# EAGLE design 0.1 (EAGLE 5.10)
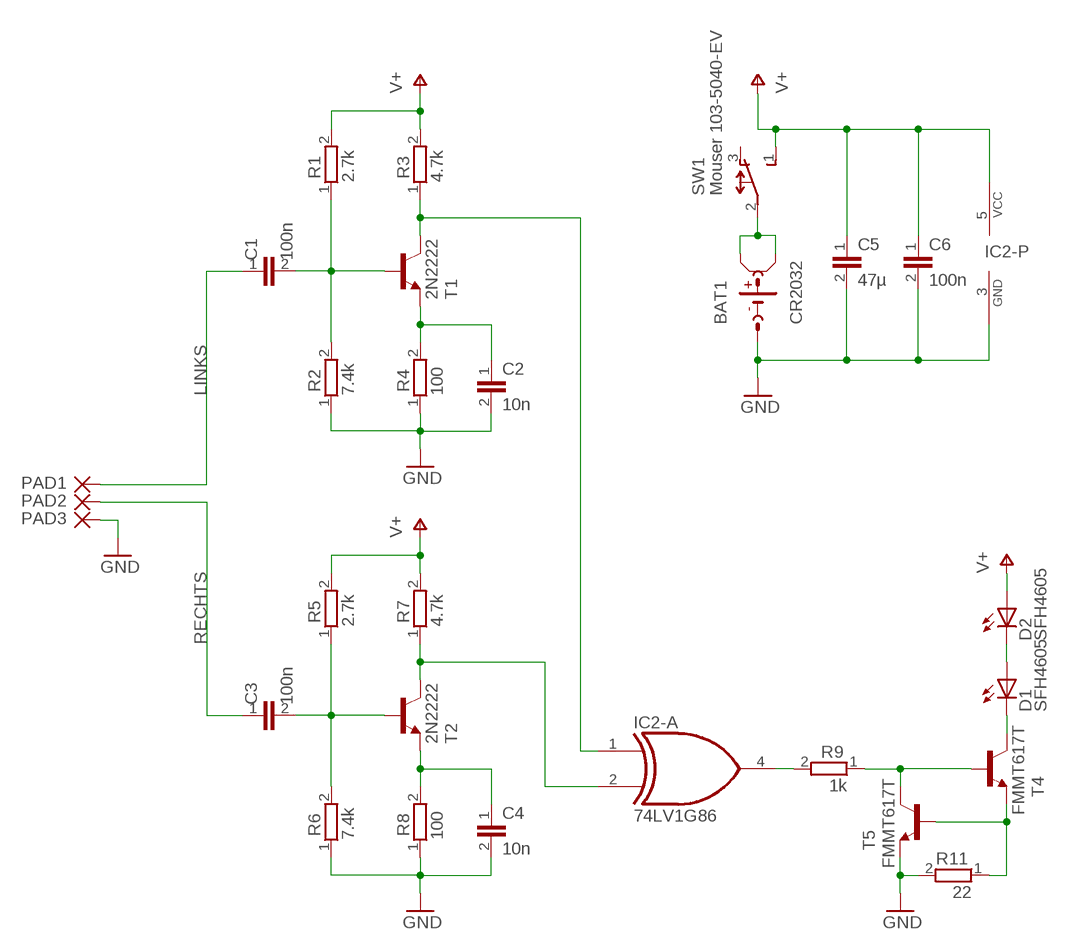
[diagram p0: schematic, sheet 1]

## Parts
BAT1  CR2032  CR2032_2+_1-SKT  [CR2032-SOCKET-THT]
C1  100n  C-0805  [0805]
C2  10n  C-0805  [0805]
C3  100n  C-0805  [0805]
C4  10n  C-0805  [0805]
C5  47µ  C-1206  [1206]
C6  100n  C-0805  [0805]
D1  SFH4605  SIDELEDB  [OSRAM-SIDELED_R]
D2  SFH4605  SIDELEDB  [OSRAM-SIDELED_R]
IC2  74LV1G86  74X1G86  [SOT23-5]
PAD1  SMD2  [SMD1,27-2,54]
PAD2  SMD2  [SMD1,27-2,54]
PAD3  SMD2  [SMD1,27-2,54]
R1  2.7k  R-0805  [0805]
R2  7.4k  R-0805  [0805]
R3  4.7k  R-0805  [0805]
R4  100  R-0805  [0805]
R5  2.7k  R-0805  [0805]
R6  7.4k  R-0805  [0805]
R7  4.7k  R-0805  [0805]
R8  100  R-0805  [0805]
R9  1k  R-0805  [0805]
R11  22  R-0805  [0805]
SW1  Mouser 103-5040-EV  IPOD-MINI-SW-2  [6.7MM_V2]
T1  2N2222  MMBT2222ALT1-NPN-SOT23-BEC  [SOT23-BEC]
T2  2N2222  MMBT2222ALT1-NPN-SOT23-BEC  [SOT23-BEC]
T4  FMMT617T  MMBT2222ALT1-NPN-SOT23-BEC  [SOT23-BEC]
T5  FMMT617T  MMBT2222ALT1-NPN-SOT23-BEC  [SOT23-BEC]

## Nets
GND: BAT1.1(NEG) C2.2 C4.2 C5.2 C6.2 IC2.3(-P:GND) PAD3.1(P) R2.1 R4.1 R6.1 R8.1 R11.2 T5.E
LINKS: C1.1 PAD1.1(P)
N$1: C1.2 R1.1 R2.2 T1.B
N$2: BAT1.2(POS2) BAT1.3(POS1) SW1.2(C)
N$3: IC2.1(-A:I0) R3.1 T1.C
N$4: D1.1(A) D2.2(C)
N$5: D1.2(C) T4.C
N$6: C3.2 R5.1 R6.2 T2.B
N$7: C4.1 R8.2 T2.E
N$8: IC2.2(-A:I1) R7.1 T2.C
N$9: C2.1 R4.2 T1.E
N$10: IC2.4(-A:O) R9.2
N$12: R9.1 T4.B T5.C
N$13: R11.1 T4.E T5.B
RECHTS: C3.1 PAD2.1(P)
V+: C5.1 C6.1 D2.1(A) IC2.5(-P:VCC) R1.2 R3.2 R5.2 R7.2 SW1.1(NO)
Unconnected: SW1.3(NC)

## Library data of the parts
BAT1 = cr2032:CR2032_2+_1-
C1-C6 = rcld_own:C
D1 D2 = sideled:SIDELED
IC2 = 74X1G86:74X1G86
PAD1-PAD3 = wirepad:SMD2: SMD PAD
R1-R9 R11 = rcld_own:R
SW1 = ipod-mini-sw:IPOD-MINI-SW: Mouser Part No: 103-5040-EV
T1 T2 T4 T5 = transistor-neu-to92:*-NPN-: NPN Transistror

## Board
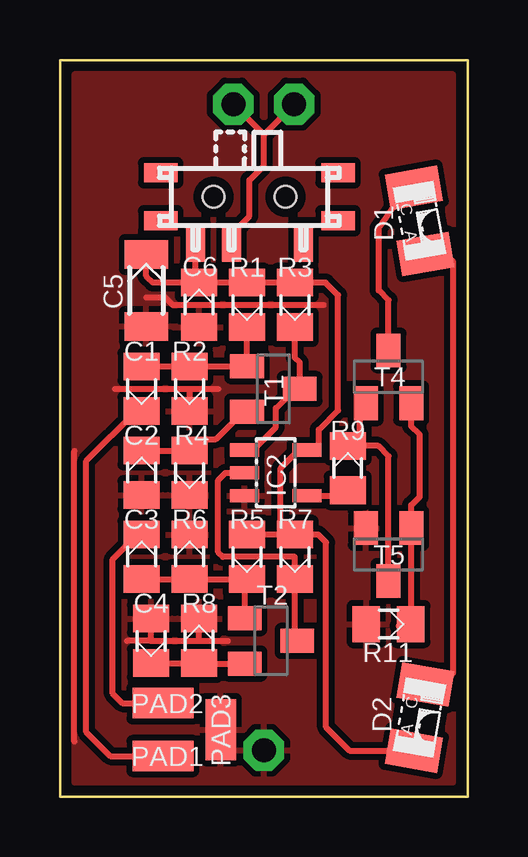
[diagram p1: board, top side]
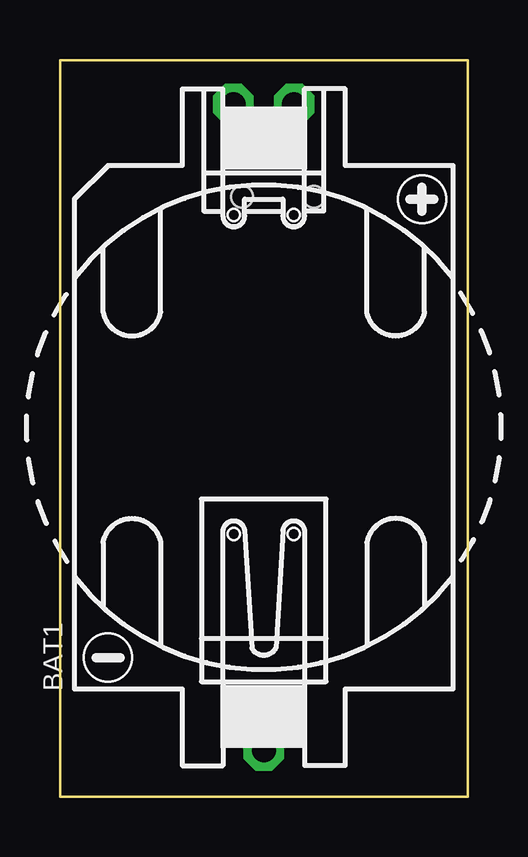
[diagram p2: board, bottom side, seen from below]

Size 17 x 30.7 mm. Coordinates in mm from the lower left corner, seen from the top.
Outline: 0,0 17,0 17,30.7 0,30.7 0,0
Copper layers (1*16): Top 0.035mm / dielectric 1.5mm / Bottom 0.035mm
Design rules "default_design_rules": minimum track width 0.1mm, minimum drill 0.3mm, track to track 10mil, track to pad 10mil, pad to pad 10mil, via to via 10mil, smd to smd 10mil, copper to edge 15mil, drill to drill 8mil, minimum pad ring 10mil, minimum via ring 8mil, stop-mask expansion 0mil, vias tented up to drill 0mil, thermal gap 10mil

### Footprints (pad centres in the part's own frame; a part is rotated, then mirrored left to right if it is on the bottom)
CR2032-SOCKET-THT = drill 1 octagon: 1 -13.462,0; 2 13.462,-1.27; 3 13.462,1.27
0805 = smd 1.15 x 1.5: 1 -0.925,0; 2 0.925,0
1206 = smd 1.2 x 1.8: 1 -1.5,0; 2 1.5,0
OSRAM-SIDELED_R = smd 1.5 x 2.2: 1 -1.4,0; 2 1.4,0
SOT23-5 = smd 0.55 x 1.2: 1 -0.95,-1.3; 2 0,-1.3; 3 0.95,-1.3; 4 0.95,1.3; 5 -0.95,1.3
SMD1,27-2,54 = smd 1.27 x 2.54: 1 0,0
6.7MM_V2 = smd 0.8 x 1.6: 1 -2.25,-1.9; 2 -0.75,-1.9; 3 2.25,-1.9 | smd 1.4 x 0.8: S1 -3.7,1; S2 -3.7,-1; S3 3.7,-1; S4 3.7,1 | hole 0.9: -1.5,0; 1.5,0
SOT23-BEC = smd 1 x 1.4: B -0.95,-1.1; C 0,1.1; E 0.95,-1.1

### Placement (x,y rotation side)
BAT1  8.5,15.4 90 bottom
C1  3.4,17 90 top
C2  3.4,13.5 270 top
C3  3.4,10 270 top
C4  3.8,6.5 90 top
C5  3.6,21.1 270 top
C6  5.8,20.5 270 top
D1  15,24 100 top
D2  15,3.3 80 top
IC2  9,13.5 270 top
PAD1  4.3,1.7 90 top
PAD2  4.3,3.9 90 top
PAD3  6.7,2.8 180 top
R1  7.8,20.5 90 top
R2  5.4,17 90 top
R3  9.8,20.5 90 top
R4  5.4,13.5 90 top
R5  7.8,10 90 top
R6  5.4,10 270 top
R7  9.8,10 90 top
R8  5.8,6.5 270 top
R9  12,13.7 270 top
R11  13.7,7.2 180 top
SW1  7.9,25 0 top
T1  8.9,17 270 top
T2  8.8,6.5 270 top
T4  13.7,17.5 0 top
T5  13.7,10.1 180 top

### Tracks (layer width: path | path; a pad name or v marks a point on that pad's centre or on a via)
GND
  Top 0.25: 11,20.5 4.7,20.5 4.4,20.8 3.6,20.8 | 5.4,17 R2.1 | 2.3,17 5.4,17 | 5.8,6.5 R8.1 | 5.8,6.5 7,6.5 | 0.6,2.3 0.6,14.4 | 5.4,17 6.6,17 | 3.8,6.5 5.8,6.5 | 3.8,6.5 2.8,6.5 | 3.8,6.5 3.8,7.5
  pour Top: 0.6,0.6 16.4,0.6 16.4,30.1 0.6,30.1
LINKS
  Top 0.25: C1.1 3.17,16.07 1.1,14 1.1,2.7 2.1,1.7 PAD1.1
N$1
  Top 0.25: R1.1 T1.B 5.4,17.95 | 5.4,17.95 3.42,17.95 C1.2 | 5.4,17.95 R2.2
N$2
  Top 0.25: SW1.2 7.15,23.45 7.9,24.2 7.9,25.7 8.5,26.3 8.5,27.59 | 8.5,27.59 BAT1.2 | 8.5,27.59 BAT1.3
N$3
  Top 0.25: R3.1 9.8,18.3 10,18.1 T1.C 9.8,17 9,16.2 9,15.4 8.05,14.45 IC2.1
N$4
  Top 0.25: D2.2 16.4,5.15 16.4,22.3 15.85,22.75 D1.1
N$5
  Top 0.25: D1.2 14.44,25.34 13.3,23.7 13.3,21.1 13.7,20.7 T4.C
N$6
  Top 0.25: C3.2 R6.2 R5.1 7.7,8.97 T2.B
N$7
  Top 0.25: C4.1 R8.2 5.83,5.55 T2.E
N$8
  Top 0.25: IC2.2 6.9,13.5 6.6,13.2 6.6,10.2 6.8,10 9.8,10 R7.1 9.8,6.6 T2.C
N$9
  Top 0.25: C2.1 R4.2 5.62,14.43 6.1,14.9 6.5,14.9 7.65,16.05 T1.E
N$10
  Top 0.25: IC2.4 12,12.55 R9.2
N$12
  Top 0.25: T5.C 13.7,14.2 13.28,14.62 12.5,14.62 | 12.5,14.62 R9.1 | T4.B 12.75,16.15 12.5,15.9 12.5,14.62
N$13
  Top 0.25: T4.E 14.65,15.45 15,15.1 15,12.5 14.65,12.15 T5.B 14.65,7.65 14.12,7.12 R11.1
RECHTS
  Top 0.25: C3.1 3.23,10.93 2.2,9.9 2.2,4.3 2.6,3.9 PAD2.1
V+
  Top 0.25: 9.2,10.93 R7.2 10.78,10.93 11.1,10.6 11.1,2.9 12.08,1.92 D2.1 | 9.2,10.93 R5.2 | C6.1 R1.2 R3.2 11.07,21.43 11.6,20.9 11.6,16.1 10.8,15.3 10.8,14.45 IC2.5 9.95,14.45 9.2,13.7 9.2,10.93 | C6.1 3.88,21.43 3.6,21.7 C5.1 | SW1.1 5.65,21.48 C6.1
(copper drawn outside any net)
  shapes: Top circle x2

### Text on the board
tTest: 17.0 | 30.7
